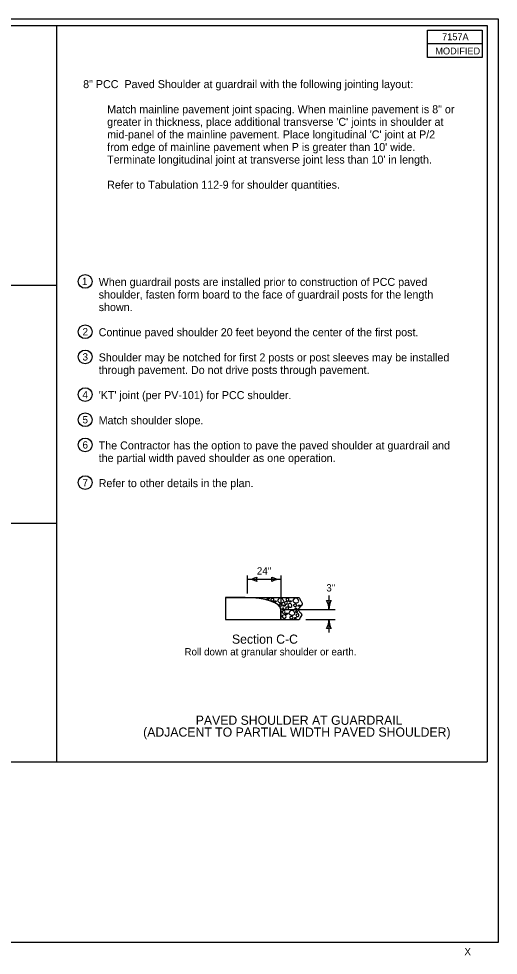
# Model space of a CAD drawing. Extents: x 9538 to 81668, y 7600 to 11751.
# Drawn here: x 19420 to 20468, y 7896 to 9944 of the extents above; entities that cross this region are included whole.
import ezdxf

# ---------------------------------------------------------------- set-up
doc = ezdxf.new("R2010")
doc.units = 0
for name, color, linetype in [('Default', 7, 'Continuous'), ('DsnShtMinorGrid12', 7, 'Continuous'), ('DsnShtMinorGrid13', 7, 'Continuous'), ('dsnStdBlockNotModified', 7, 'Continuous'), ('dsnStdCells', 7, 'Continuous'), ('dsnStdDimension', 7, 'Continuous'), ('dsnStdNameDate', 7, 'Continuous'), ('dsnStdNote', 7, 'Continuous'), ('dsnStdShading', 7, 'Continuous'), ('dsnStdTable', 7, 'Continuous'), ('Level 9', 7, 'Continuous')]:
    doc.layers.add(name, color=color, linetype=linetype)

msp = doc.modelspace()

# ---------------------------------------------------------------- linework, layer by layer
at = {"layer": 'Default'}
msp.add_lwpolyline([(17332.5, 9944), (20467.5, 9944), (20467.5, 7924), (17332.5, 7924)], close=True, dxfattribs=at)
at = {"layer": 'DsnShtMinorGrid12'}
for points in [[(19964.3, 8674.1), (19965.1, 8673.9), (19965.7, 8673.9), (19968.1, 8676.3), (19964.1, 8677.1), (19960.6, 8675), (19963.4, 8674.3), (19964.3, 8674.1)], [(19970.7, 8674.6), (19970.8, 8675.1), (19971.1, 8675), (19975.7, 8677.6), (19978.1, 8674.4), (19975.9, 8670.4), (19970.9, 8671.5), (19970.7, 8674), (19970.7, 8674.6)], [(19979.9, 8668.6), (19980.8, 8668.4), (19981.3, 8668.4), (19983.7, 8670.8), (19979.7, 8671.6), (19976.2, 8669.5), (19979.1, 8668.7), (19979.9, 8668.6)], [(19985.6, 8670.8), (19985.3, 8671.3), (19985.9, 8670.9), (19987.7, 8677.4), (19996, 8677.6), (19998.7, 8670.4), (19999, 8669.6), (19994.2, 8665.8), (19987.5, 8668), (19985.9, 8670.3), (19985.6, 8670.8)], [(19989.1, 8663.3), (19989.1, 8663.9), (19989.5, 8663.7), (19994.1, 8666.4), (19996.5, 8663.2), (19994.3, 8659.2), (19989.2, 8660.2), (19989.1, 8662.7), (19989.1, 8663.3)], [(20000.1, 8667.4), (20000.2, 8668), (20000.5, 8667.8), (20005.1, 8670.5), (20007.5, 8667.3), (20005.3, 8663.2), (20000.2, 8664.3), (20000.1, 8666.8), (20000.1, 8667.4)], [(20003.7, 8674.6), (20003.7, 8675.1), (20004.1, 8675), (20008.6, 8677.6), (20011, 8674.4), (20008.9, 8670.4), (20003.8, 8671.5), (20003.6, 8674), (20003.7, 8674.6)], [(20008.2, 8661.4), (20007.6, 8662.5), (20007.8, 8662.9), (20012.4, 8665.8), (20016.4, 8664), (20017.4, 8658.6), (20011.3, 8655.9), (20008.8, 8660.2), (20008.2, 8661.4)], [(20012.8, 8668.6), (20013.7, 8668.4), (20014.2, 8668.4), (20016.6, 8670.8), (20012.6, 8671.6), (20009.1, 8669.5), (20012, 8668.7), (20012.8, 8668.6)], [(20018.5, 8670.8), (20018.3, 8671.3), (20018.8, 8670.9), (20020.7, 8677.4), (20029, 8677.6), (20031.6, 8670.4), (20031.9, 8669.6), (20027.1, 8665.8), (20020.4, 8668), (20018.8, 8670.3), (20018.5, 8670.8)], [(20020.4, 8662), (20020.4, 8662.6), (20020.8, 8662.4), (20025.3, 8665.1), (20027.8, 8661.9), (20025.6, 8657.9), (20020.5, 8658.9), (20020.3, 8661.4), (20020.4, 8662)], [(19994.5, 8653.6), (19994.1, 8654.1), (19994.4, 8654.5), (19998.7, 8655.8), (20000.1, 8652.3), (19996.8, 8651.5), (19994.9, 8653.2), (19994.5, 8653.6)], [(19995.2, 8647.4), (19995.3, 8648), (19995.6, 8647.8), (20000.2, 8650.5), (20002.6, 8647.3), (20000.5, 8643.3), (19995.4, 8644.3), (19995.2, 8646.8), (19995.2, 8647.4)], [(19999.2, 8659.3), (20000.1, 8659.1), (20000.6, 8659.1), (20003, 8661.6), (19999, 8662.4), (19995.5, 8660.2), (19998.4, 8659.5), (19999.2, 8659.3)], [(20004.4, 8641.4), (20005.3, 8641.3), (20005.8, 8641.3), (20008.2, 8643.7), (20004.2, 8644.5), (20000.7, 8642.3), (20003.6, 8641.6), (20004.4, 8641.4)], [(20003, 8655.6), (20003, 8656.2), (20003.4, 8656), (20007.9, 8658.7), (20010.3, 8655.4), (20008.2, 8651.4), (20003.1, 8652.5), (20002.9, 8655), (20003, 8655.6)], [(20010.1, 8643.7), (20009.8, 8644.2), (20010.4, 8643.8), (20012.2, 8650.2), (20020.5, 8650.5), (20023.2, 8643.3), (20023.5, 8642.5), (20018.7, 8638.7), (20012, 8640.9), (20010.4, 8643.2), (20010.1, 8643.7)], [(20023.1, 8653.2), (20022.7, 8653.7), (20023.1, 8654.1), (20027.4, 8655.4), (20028.7, 8651.9), (20025.5, 8651.1), (20023.5, 8652.7), (20023.1, 8653.2)], [(20024.4, 8647.1), (20024, 8647.6), (20024.4, 8648), (20028.7, 8649.3), (20030, 8645.8), (20026.8, 8645), (20024.8, 8646.6), (20024.4, 8647.1)], [(20032.1, 8659.3), (20033, 8659.1), (20033.5, 8659.1), (20035.9, 8661.6), (20031.9, 8662.4), (20028.4, 8660.2), (20031.3, 8659.5), (20032.1, 8659.3)], [(19995.6, 8636.9), (19995.1, 8638), (19995.2, 8638.4), (19999.8, 8641.3), (20003.8, 8639.4), (20004.9, 8634.1), (19998.7, 8631.4), (19996.2, 8635.7), (19995.6, 8636.9)], [(20012, 8634.9), (20012, 8635.5), (20012.4, 8635.3), (20016.9, 8638), (20019.3, 8634.7), (20017.2, 8630.7), (20012.1, 8631.8), (20011.9, 8634.3), (20012, 8634.9)], [(20023.7, 8632.2), (20024.6, 8632), (20025.1, 8632), (20027.5, 8634.4), (20023.5, 8635.2), (20020, 8633.1), (20022.9, 8632.4), (20023.7, 8632.2)], [(20025.6, 8640.3), (20025.6, 8640.9), (20026, 8640.7), (20030.5, 8643.4), (20032.9, 8640.2), (20030.8, 8636.2), (20025.7, 8637.2), (20025.5, 8639.7), (20025.6, 8640.3)]]:
    msp.add_open_spline(points, degree=3, dxfattribs=at)
at = {"layer": 'DsnShtMinorGrid13'}
for centre in [(19564.9, 9369.6), (19564.9, 9259.6), (19564.9, 9204.6), (19564.9, 9122.1), (19564.9, 9067.1), (19564.9, 9012.1), (19564.9, 8929.6)]:
    msp.add_circle(centre, 15, dxfattribs=at)
at = {"layer": 'dsnStdCells'}
for p, q in [((19914.7, 8678.3), (19871.6, 8678.3)), ((19871.6, 8678.3), (19871.6, 8630.3)), ((19992.5, 8630.3), (19992.5, 8652.1)), ((19871.6, 8630.3), (19992.5, 8630.3))]:
    msp.add_line(p, q, dxfattribs=at)
msp.add_lwpolyline([(19914.7, 8678.3), (19914.7, 8678.3)], dxfattribs=at)
msp.add_ellipse((19914.7, 8652.1), major_axis=(77.9, 0), ratio=0.335273, start_param=0, end_param=1.570796, dxfattribs=at)
at = {"layer": 'dsnStdDimension'}
for p, q in [((19920, 8686.8), (19920, 8726.2)), ((19992.5, 8726.2), (19992.5, 8662.7)), ((19920, 8718.2), (19992.5, 8718.2)), ((20097.6, 8683.1), (20097.6, 8652.1)), ((19999.4, 8652.1), (20111.4, 8652.1)), ((20047.3, 8630.3), (20111.4, 8630.3)), ((20097.6, 8630.3), (20097.6, 8601.7))]:
    msp.add_line(p, q, dxfattribs=at)
for centre, radius, start, end in [((19920, 8760.7), 42.5, 270, 298.0725), ((19920, 8675.7), 42.5, 61.9275, 90), ((19955.6, 8718.2), 16.4, 162.2666, 197.7334), ((19956.9, 8718.2), 16.4, 342.2666, 17.7334), ((19992.5, 8760.7), 42.5, 241.9275, 270), ((19992.5, 8675.7), 42.5, 90, 118.0725), ((20097.6, 8687.8), 16.4, 252.2666, 287.7334), ((20055.1, 8652.1), 42.5, 0, 28.0725), ((20140.1, 8652.1), 42.5, 151.9275, 180), ((20055.1, 8630.3), 42.5, 331.9275, 360), ((20140.1, 8630.3), 42.5, 180, 208.0725), ((20097.6, 8594.7), 16.4, 72.2666, 107.7334)]:
    msp.add_arc(centre, radius, start, end, dxfattribs=at)
at = {"layer": 'dsnStdNameDate'}
for p, q in [((19503.1, 8319), (19503.1, 9929)), ((19503.1, 9361), (17347.5, 9361)), ((19503.1, 8840), (17347.5, 8840))]:
    msp.add_line(p, q, dxfattribs=at)
at = {"layer": 'dsnStdShading'}
for p, q in [((17347.5, 9929), (20443.2, 9929)), ((20443.2, 9929), (20443.2, 8319)), ((17347.5, 8319), (20443.2, 8319))]:
    msp.add_line(p, q, dxfattribs=at)
at = {"layer": 'dsnStdTable'}
for p, q in [((20443.2, 9929), (20443.2, 9929)), ((19871.6, 8678.3), (19871.6, 8630.3)), ((19871.6, 8678.3), (19914.7, 8678.3)), ((19914.7, 8678.3), (20032.4, 8678.3)), ((19992.5, 8652.1), (19992.5, 8630.3)), ((19871.6, 8630.3), (19992.5, 8630.3)), ((19992.5, 8630.3), (20032.4, 8630.3))]:
    msp.add_line(p, q, dxfattribs=at)
msp.add_lwpolyline([(20432.3, 9919), (20432.3, 9859), (20312.6, 9859), (20312.6, 9919), (20432.3, 9919), (20432.3, 9889), (20312.6, 9889)], dxfattribs=at)
msp.add_ellipse((19914.7, 8652.1), major_axis=(77.9, 0), ratio=0.335273, start_param=0, end_param=1.570796, dxfattribs=at)
msp.add_spline([(20032.4, 8678.3), (20033.8, 8675.1), (20035.7, 8671.9), (20037.5, 8668.9), (20039, 8665.8), (20039.1, 8664.1), (20038.4, 8662.3), (20035.6, 8658.8), (20032.4, 8655.3), (20031.3, 8653.6), (20031, 8652.7), (20030.8, 8651.8), (20030.8, 8651.4), (20031.2, 8650.2), (20032.2, 8648.7), (20035.1, 8645.5), (20037.6, 8642.3), (20038.1, 8640.7), (20038, 8639.9), (20037.9, 8639.5), (20037.7, 8639.1), (20032.3, 8630.4)], degree=3, dxfattribs=at)

# ---------------------------------------------------------------- texts
at = {"layer": 'DsnShtMinorGrid13'}
for s, height, p in [('8" PCC  Paved Shoulder at guardrail with the following jointing layout:', 17.5, (19560.5, 9792.3)), ('Match mainline pavement joint spacing. When mainline pavement is 8" or ', 17.5, (19613, 9737.3)), ("greater in thickness, place additional transverse 'C' joints in shoulder at ", 17.5, (19613, 9709.8)), ("mid-panel of the mainline pavement. Place longitudinal 'C' joint at P/2 ", 17.5, (19613, 9682.3)), ("from edge of mainline pavement when P is greater than 10' wide. ", 17.5, (19613, 9654.8)), ("Terminate longitudinal joint at transverse joint less than 10' in length.", 17.5, (19613, 9627.3)), ('Refer to Tabulation 112-9 for shoulder quantities.', 17.5, (19613, 9572.3)), ('1', 16, (19558.1, 9361.6)), ('When guardrail posts are installed prior to construction of PCC paved ', 17.5, (19594.5, 9359.7)), ('shoulder, fasten form board to the face of guardrail posts for the length ', 17.5, (19594.5, 9332.2)), ('shown.', 17.5, (19594.5, 9304.7)), ('2', 16, (19559.3, 9251.6)), ('Continue paved shoulder 20 feet beyond the center of the first post.', 17.5, (19594.5, 9249.7)), ('3', 16, (19559.2, 9196.6)), ('Shoulder may be notched for first 2 posts or post sleeves may be installed ', 17.5, (19594.5, 9194.7)), ('through pavement. Do not drive posts through pavement.', 17.5, (19594.5, 9167.2)), ('4', 16, (19559.3, 9114.1)), ("'KT' joint (per PV-101) for PCC shoulder.", 17.5, (19594.5, 9112.2)), ('5', 16, (19559.2, 9059.1)), ('Match shoulder slope.', 17.5, (19594.5, 9057.2)), ('6', 16, (19559.2, 9004.1)), ('The Contractor has the option to pave the paved shoulder at guardrail and ', 17.5, (19594.5, 9002.2)), ('the partial width paved shoulder as one operation.', 17.5, (19594.5, 8974.7)), ('7', 16, (19559.2, 8921.6)), ('Refer to other details in the plan.', 17.5, (19594.5, 8919.7))]:
    msp.add_text(s, height=height, dxfattribs=at).set_placement(p)
at = {"layer": 'dsnStdBlockNotModified'}
msp.add_text('X', height=16, dxfattribs=at).set_placement((20393.6, 7896))
at = {"layer": 'dsnStdDimension'}
for s, p in [("24''", (19940.1, 8728.5)), ("3'' ", (20091.9, 8691.5))]:
    msp.add_text(s, height=16, dxfattribs=at).set_placement(p)
at = {"layer": 'dsnStdNote'}
for s, height, p in [('Section C-C', 20, (19885.7, 8577.3)), ('Roll down at granular shoulder or earth.', 16, (19781.9, 8551.7)), ('PAVED SHOULDER AT GUARDRAIL', 20, (19806.5, 8400)), ('(ADJACENT TO PARTIAL WIDTH PAVED SHOULDER)', 20, (19691.6, 8374.1))]:
    msp.add_text(s, height=height, dxfattribs=at).set_placement(p)
at = {"layer": 'Level 9'}
for s, p in [('7157A', (20344.8, 9897)), ('MODIFIED', (20330, 9866))]:
    msp.add_text(s, height=15, dxfattribs=at).set_placement(p)

doc.saveas('drawing.dxf')
